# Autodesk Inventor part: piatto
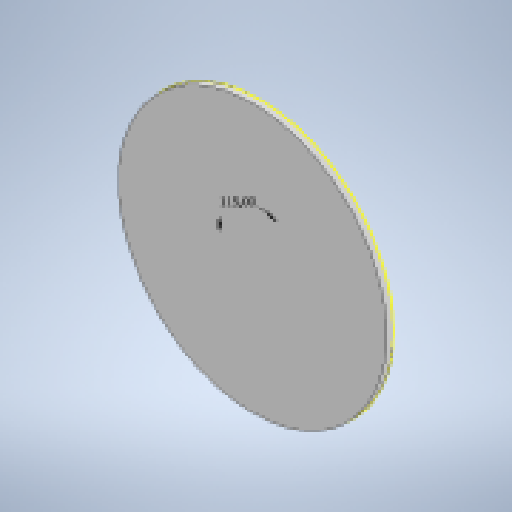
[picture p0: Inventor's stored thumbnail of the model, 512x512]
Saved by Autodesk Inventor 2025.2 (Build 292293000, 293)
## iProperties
Created: 2025-03
Part Number: piatto
Material: Generico
Document SubType Name: Modeling
Designer: 18907419
Density: 1 g/cm^3
Appearance: Default
Author: 18907419
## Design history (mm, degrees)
sketch "Schizzo1"
  geometry: C1 r 100 at (0, 28.5); A1 r 55 centre (0, 28.5) between (-51.459, 47.916) and (47.95, 1.56) reference; 1 further point
  constraints: 1 centre point, 1 coincident
  dimensions: "d0" = 200 diameter of C1
extrude "Estrusione1" new body sketch "Schizzo1" distance "d1" = 5; taper "d2" = 0 deg
sketch "Schizzo2"
  geometry: L1 (0, 0)-(-42.262, 90.631); L2 (0, 0)-(100, 0); A1 r 55 centre (0, 0) between (47.95, 26.94) and (-51.459, -19.416) reference; 3 further points
  constraints: 4 end point, 1 equal length, 1 horizontal, 1 point on line, 2 other
  dimensions: "d3" = 115 deg angle of L2 L1; "d11" = 90 distance of L1.start point (-38.036, 81.568)
hole "Foro1" sketch "Schizzo2" at (-38.036, 81.568) diameter "d4" = 8; stored, may be unused: countersink angle "d8" = 90 deg, drill point angle "d10" = 118 deg; dims "d5" = 6, "d6" = 4, "d7" = 2, "d9" = 8
node "Solido1"
node "Riferimento1"
node "Riferimento2"
